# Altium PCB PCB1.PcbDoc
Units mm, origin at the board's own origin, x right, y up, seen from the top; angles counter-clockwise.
Board outline 72.64 x 51.05 mm, 2 copper layers (Top Layer, Bottom Layer); 19 components, 17 nets, 61 pads, 2 vias.
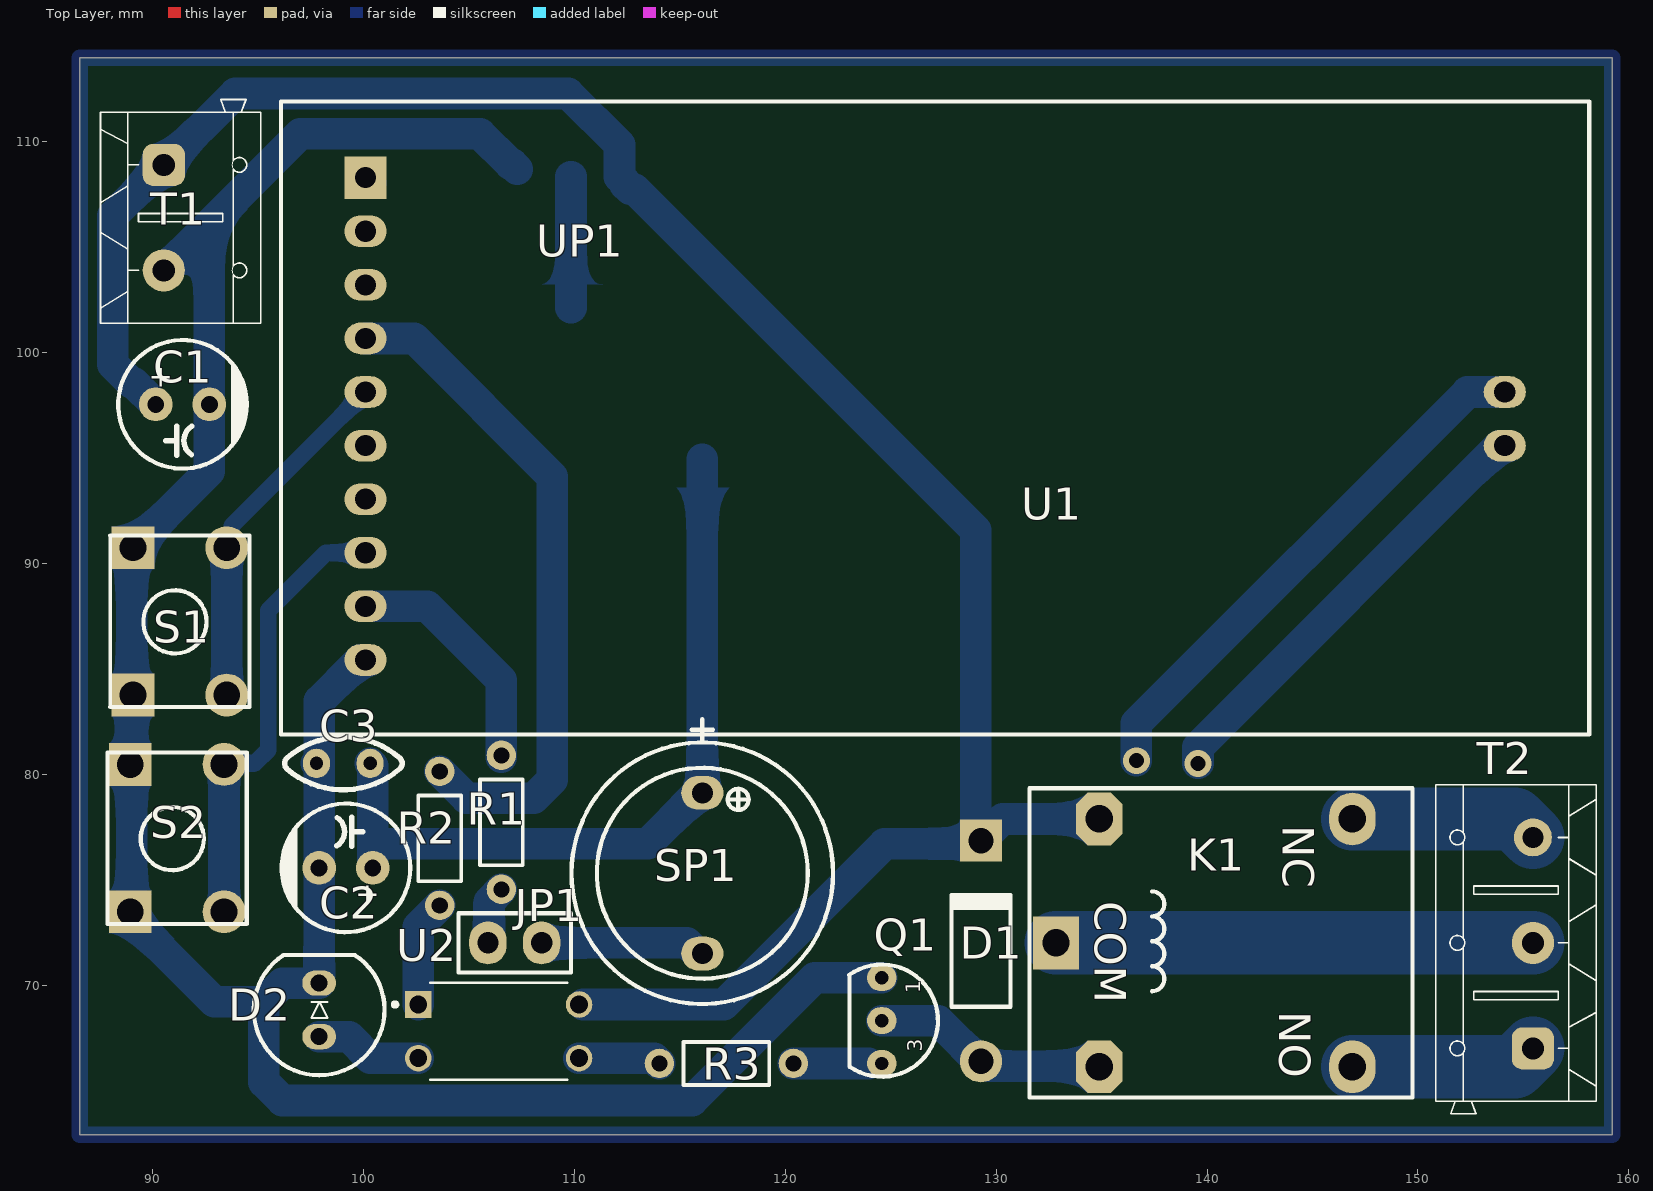
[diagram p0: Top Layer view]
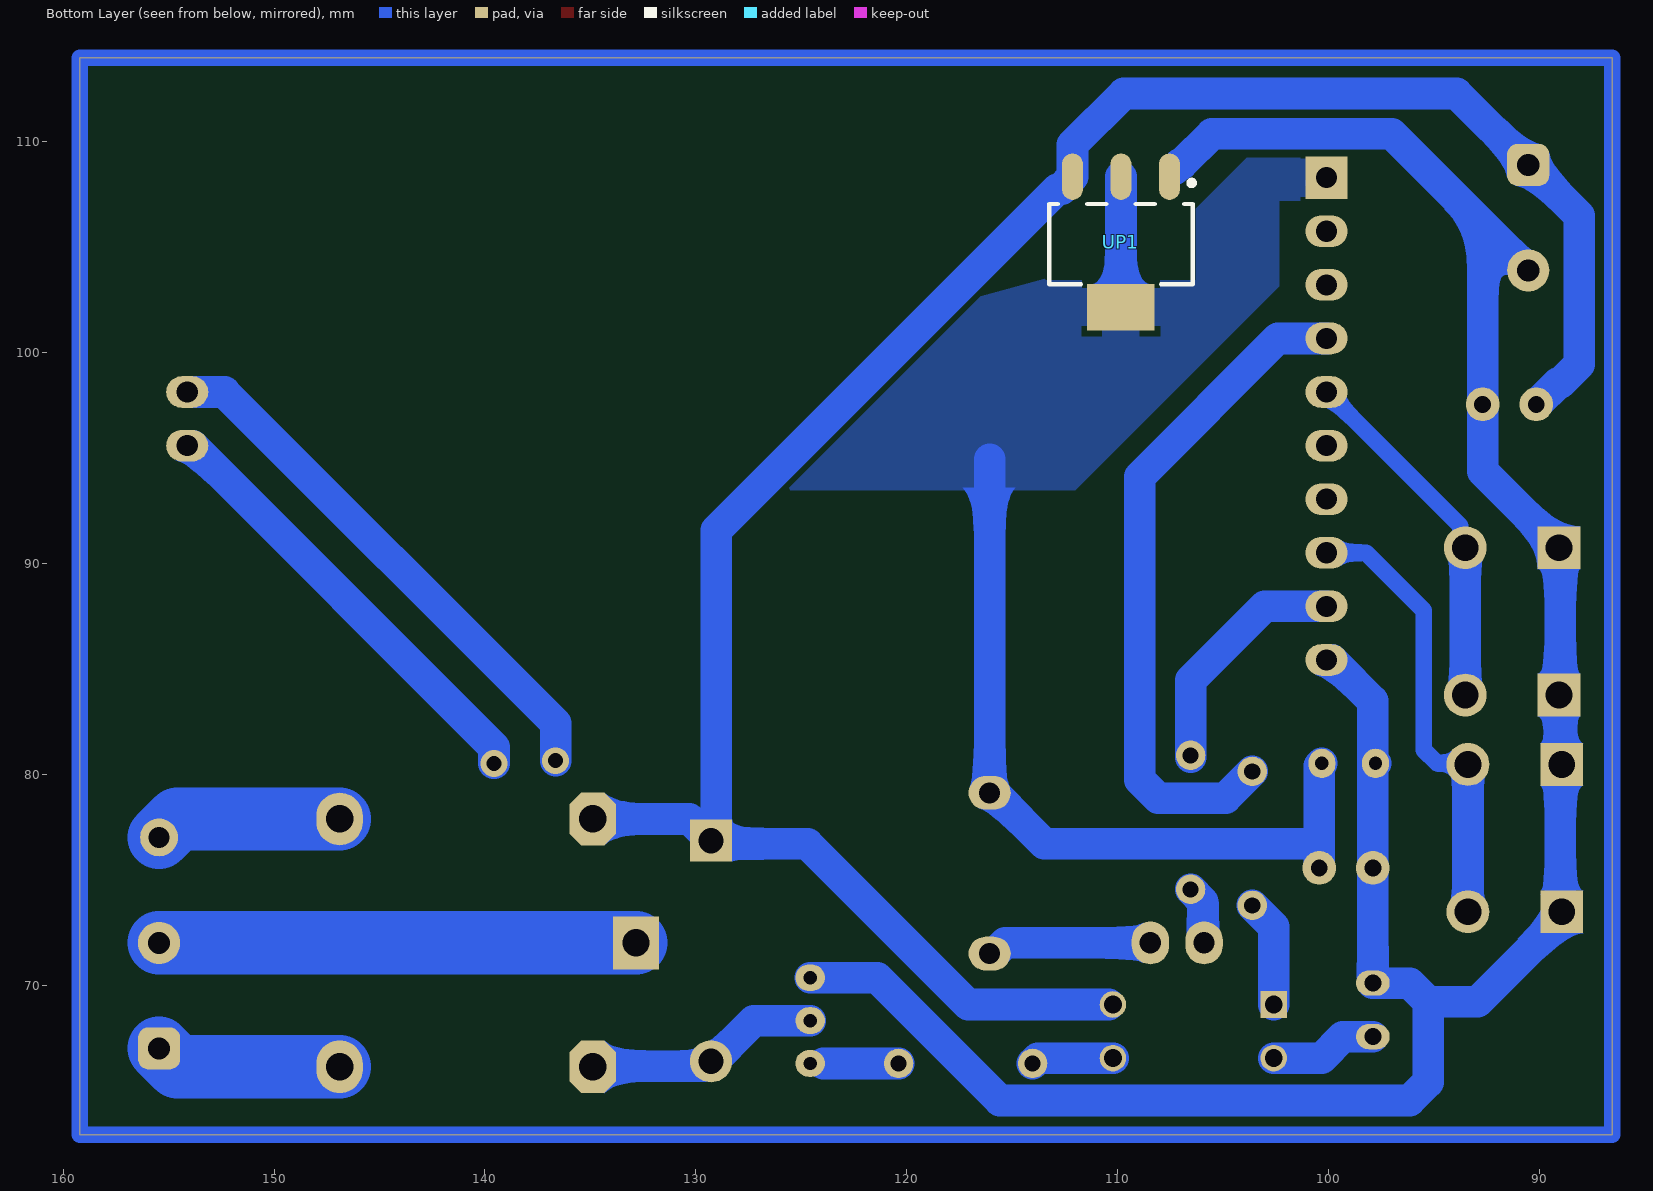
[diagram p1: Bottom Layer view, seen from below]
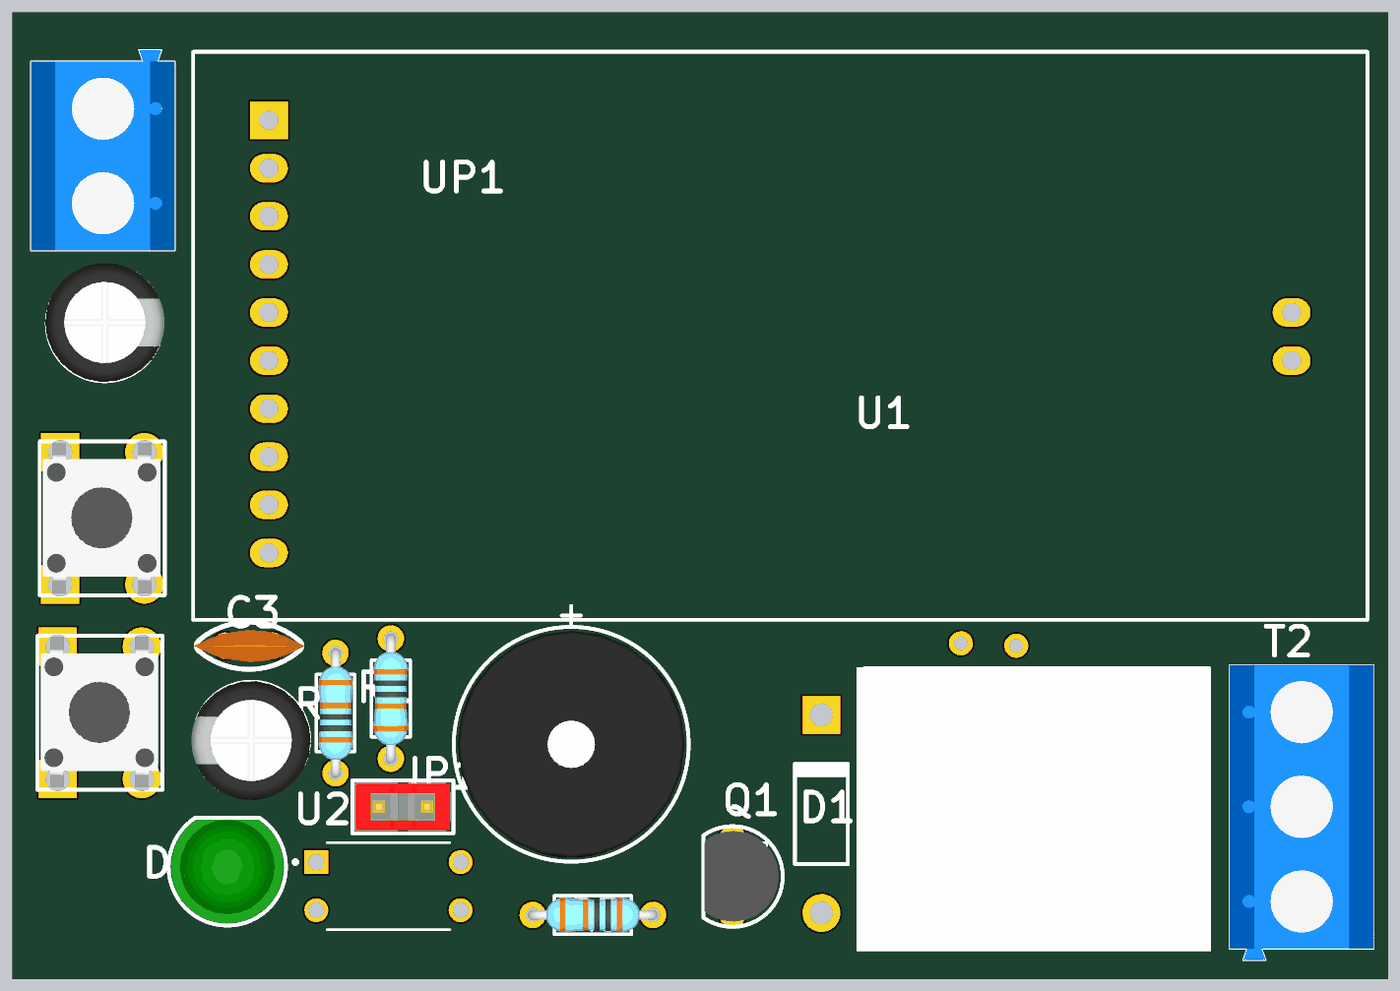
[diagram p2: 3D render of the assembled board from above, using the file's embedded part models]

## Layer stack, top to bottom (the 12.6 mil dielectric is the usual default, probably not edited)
Top Solder: solder mask 0.0102, Solder Resist, Dk 3.5
Top Layer: signal copper 0.0356
Dielectric 1: dielectric 0.32, FR-4, Dk 4.8
Bottom Layer: signal copper 0.0356
Bottom Solder: solder mask 0.0102, Solder Resist, Dk 3.5

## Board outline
86.567,62.912 86.567,113.966 159.211,113.966 159.211,62.912

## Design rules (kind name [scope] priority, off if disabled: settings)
Clearance [All] p1: gap=0.254 ignorepadtopadclearanceinfootprint=FALSE except(0: Arc-Hole Track-Hole SMDPad-Hole THPad-Hole Via-Hole Fill-Hole Poly-Hole Region-Hole Text-Hole)
PolygonConnect [All] p1: connectstyle=Relief reliefconductorwidth=1.8 reliefentries=4 polygonreliefangle="90 Angle" airgapwidth=0.254
RoutingVias [All] p1: holewidth=0.711 width=1.27 viastyle="Through Hole" minholewidth=0.711 minwidth=1.27 maxholewidth=0.711 maxwidth=1.27
SolderMaskExpansion [All] p1: expansion=0.102 istentingtop=FALSE
Width [All] p1: maxlimit=3 minlimit=0.8 preferedwidth=1.5
30 further rules are at their usual default settings.

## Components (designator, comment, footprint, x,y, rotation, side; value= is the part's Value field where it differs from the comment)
C1 "100uf" "Cap electrolitic radial 6.3x12-2.5" 90.17,97.536 r0 top value=1uF
C2 "100uf" "Cap electrolitic radial 6.3x12-2.5" 100.457,75.565 r180 top value=1uF
C3 "100nF" Cap-100nF 99.06,80.518 r0 top
D1 "Diode 1N4007" DO-41 129.286,71.628 r90 top
D2 "LED 5MM" LED5MM_GRN 97.917,68.834 r90 top
JP1 "Jumper 2Pin" "Jumper Small - 2.54 - Black" 107.188,72.009 r180 top
K1 "" "Relay 18.85x15.35x15.70" 139.867,72.009 r270 top
Q1 "C945" C945 124.587,68.326 r90 top
R1 "10" RES-(1/4) 106.553,77.724 r270 top
R2 "1K" RES-(1/4) 103.632,76.962 r90 top
R3 "2.2K" RES-(1/4) 117.221,66.294 r180 top
S1 "Switch PB" "Switch - Push to On" 91.313,87.249 r90 top
S2 "Switch PB" "Switch - Push to On" 91.186,76.975 r90 top
SP1 "" "BUZZER 7.62mm DC" 116.078,75.311 r270 top
T1 "KF301_Terminal" "KF301 2PIN" 90.551,106.386 r270 top
T2 "KF301_Terminal" "KF301 3PIN" 155.448,72.009 r90 top
U1 "RFID" RFID 126.746,96.139 r0 top
U2 "PC817X3NSZ1B" DIP762W50P254L495H455Q4 106.426,67.818 r0 top
UP1 "AMS1117_5V" SOT223 109.855,105.129 r270 bottom

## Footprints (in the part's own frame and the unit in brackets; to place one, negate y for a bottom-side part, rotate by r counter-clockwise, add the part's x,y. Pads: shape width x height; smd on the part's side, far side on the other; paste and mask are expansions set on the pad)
"BUZZER 7.62mm DC" [mm] "BUZZER 12mm DIA , 7.62mm pitch DESIGNER ABBAS BASEREH"
  oval 1.6x2 hole 1: 1(-3.81,0) 2(3.81,0)
  silkscreen extent -7.3,-6.2 6.2,6.2, body extent -6,-6 6,6, height 9.5
C945 [mil] "NPN Transistor"
  oval 50x55 hole 25: 1(80,0) 2(0,0) 3(-80,0)
  silkscreen extent -105,-105 105,61, body extent -94,-96 95,58, height 315
"Cap electrolitic radial 6.3x12-2.5" [mm] "Capacitor Electrolytic D=6.3 x H=12 - P=2.5 mm, Altium Compatible"
  round 1.6 hole 0.8: 1(0,0) 2(2.54,0)
  silkscreen extent -1.77,-3.05 4.32,3.05, body extent -1.87,-3.09 4.43,3.2, height 1.2
Cap-100nF [mil] "Bipolar Capacitor-Design:Ali Hafizi"
  oval 50x55 hole 25: 1(-50,0) 2(50,0)
  silkscreen extent -110,-49 110,49, body extent -115,-34 115,33, height 272
DIP762W50P254L495H455Q4 [mm]
  rect 1.26x1.26 hole 0.84: 1(-3.81,1.27)
  round 1.26 hole 0.84: 2(-3.81,-1.27) 3(3.81,-1.27) 4(3.81,1.27)
  silkscreen extent -5.01,-2.3 3.25,2.3
DO-41 [mm] "Diode, Axial; Body 5.2 x 2.7 mm (LxDia. max), Lead Dia. 0.86 mm (max)"
  round 2 hole 1.2: 1(-5.23,0)
  rect 2x2 hole 1.2: 2(5.23,0)
  silkscreen extent -2.65,-1.4 2.75,1.4
"Jumper Small - 2.54 - Black" [mil] "Designer Abbas Basereh"
  oval 70x80 hole 40: 1(-50,0) 2(50,0)
  silkscreen extent -105,-55 105,55, body extent -100,-50 100,50, height 337
"KF301 2PIN" [mm] "Designer Abbas Basereh"
  rrect50% 2x2 hole 1.05: 1(-2.5,0)
  round 2 hole 1.05: 2(2.5,0)
  silkscreen extent -5.6,-3 5,4.6, body extent -5.6,-3 5,4.6, height 10
"KF301 3PIN" [mm] "Designer Abbas Basereh"
  rrect50% 2x2 hole 1.05: 1(-5,0)
  round 2 hole 1.05: 2(0,0)
  round 1.8 hole 1: 3(5,0)
  silkscreen extent -8.1,-3 7.5,4.6, body extent -8.1,-3 7.5,4.6, height 10
LED5MM_GRN [mm] "LED 5MM THROUGH HOLE GREEN-Designer Abbas Basereh"
  oval 1.2x1.6 hole 0.8: 1(-1.27,0) 2(1.27,0)
  silkscreen extent -3.1,-3.1 2.6,3.1, body extent -3,-3 2.5,3, height 9.14
"Relay 18.85x15.35x15.70" [mm]
  rect 2.5x2.2 hole 1.3: 1(0,-7.025)
  oval 2.5x2.2 hole 1.3: 2(-5.875,7.025) 3(5.875,7.025)
  oct 2.5x2.2 hole 1.3: 4(-5.875,-4.975) 5(5.875,-4.975)
  silkscreen extent -7.32,-8.27 7.32,9.87, body extent -7.37,-8.71 7.63,9.98, height 15.7
RES-(1/4) [mil]
  round 55 hole 30: 1(-125,0) 2(125,0)
  silkscreen extent -80,-40 80,40, body extent -135,-36 135,36, height 115
RFID [mm] "RFID 2&10 PIN"
  rect 2x2 hole 1: 1(-26.632,12.141)
  oval 2x1.5 hole 1: 2(-26.632,9.601) 3(-26.632,7.061) 4(-26.632,4.521) 5(-26.632,1.981) 6(-26.632,-0.559) 7(-26.632,-3.099) 8(-26.632,-5.639) 9(-26.632,-8.179) 10(-26.632,-10.719) 11(27.368,1.981) 12(27.368,-0.559)
  silkscreen extent -30.63,-14.25 31.37,15.75, body extent -30.63,-14.25 31.37,15.72, height 11.1
SOT223 [mm] "SOT223, 4-Leads, Body 6.5x3.5mm, Pitch 2.30mm-Designer Abbas Basereh"
  oval 2.2x1 smd: 1(-3.2,2.3) 2(-3.2,0) 3(-3.2,-2.3)
  rect 2.2x3.2 smd: 4(3,0)
  Top Layer pour cut-out: -1.7,3.556 1.7,3.556 1.7,-3.556 -1.7,-3.556
  silkscreen extent -3.02,-3.4 1.9,3.47, body extent -3.5,-3.25 3.5,3.25, height 1.7
"Switch - Push to On" [mil]
  rect 80x80 hole 50: 1(-137.5,87.5) 1(137.5,87.5)
  round 80 hole 50: 2(-137.5,-87.5) 2(137.5,-87.5)
  silkscreen extent -160,-130 160,130, body extent -155,-121 157,123, height 205

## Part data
C1 C2: library part "Cap ELECTROLITIC TOTAL SIZE", "Cap electrolitic radial"
C3: library part "CAP CERAMIC TOTAL SIZE", "CAP Ceramic Total"
D1: "1 Amp General Purpose Rectifier"
D2: "Light Emitting Diode"
JP1: "Jumper, 2-Pin"
K1: library part RELAY_SPDT, "Single-Pole Dual-Throw Relay"
Q1: "NPN Transistor"
R1 R2 R3: library part "RES DIP PACKAGE", "TOTAL DIP RESISTOR PACK"
S1 S2: "Push Button Switch"
SP1: library part "PIEZO BUZZER", "PIEZO BUZZER ACTIVE"
T1: library part KF301-2Pin_Terminal, "Terminal 2 Pin 250VAC 16A"
T2: library part KF301-3Pin_Terminal, "Terminal 3 Pin 250VAC 16A"
U2: "Optoisolator Transistor Output 1 Channel 4-DIP", Package=None
UP1: library part AMS1117-x.x, "x.x Volt, 800mA Low-Dropout Linear Regulator, 4-pin SOT-223"

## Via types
v1: diameter 1.27, hole 0.711, Top Layer to Bottom Layer, 2 vias

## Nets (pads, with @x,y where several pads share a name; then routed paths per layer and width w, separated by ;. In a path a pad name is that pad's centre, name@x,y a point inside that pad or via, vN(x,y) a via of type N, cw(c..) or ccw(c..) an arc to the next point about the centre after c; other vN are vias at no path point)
+5: C2.1 C3.2 SP1.1 U1.1 UP1.2 UP1.4 | length 44.2
  Bottom Layer w1.5: U1.1 U1.1@100.364,108.03 ; C3.2 100.457,80.391 100.457,76.708 ; C2.1 100.457,76.708 ; UP1.4 UP1.2 ; SP1.1 116.078,94.931 ; SP1.1@116.251,79.121 115.905,79.121 113.492,76.708 100.457,76.708
+12: C1.1 D1.2 K1.4 T1.1 U2.4 UP1.3 | length 105.3
  Bottom Layer w1.5: C1.1 90.143,97.536 89.117,98.562 89.017,98.562 88.138,99.441 88.138,106.473 T1.1 93.933,112.268 109.728,112.268 112.155,109.841 UP1.3 112.405,108.079 112.405,107.979 112.655,107.729 112.87,107.729 129.032,91.567 129.032,77.987 129.036,77.983 129.036,76.708 124.714,76.708 117.094,69.088 U2.4@110.438,69.088 ; D1.2 130.312,77.884 K1.4
GND: C1.2 C2.2 C3.1 D2.2 Q1.1 S1.1 S2.1 T1.2 U1.10 UP1.1 | length 117.8
  Bottom Layer w1.5: T1.2 92.71,106.045 ; U1.10 99.864,85.42 97.917,83.474 97.917,80.645 C3.1 97.917,80.391 C2.2 D2.2 96.167,70.104 95.289,69.225 ; UP1.1@107.305,108.679 107.055,108.929 106.971,108.929 105.537,110.363 97.028,110.363 92.71,106.045 ; Q1.1 121.412,70.358 115.594,64.54 96.167,64.54 95.289,65.419 95.289,69.225 ; 92.71,106.045 C1.2 92.71,94.361 89.09,90.742 89.027,90.678 89.027,83.757 89.027,80.467 89.027,73.546 88.963,73.482 89.229,73.216 89.229,72.95 92.954,69.225 95.289,69.225
NetD1_1: D1.1 K1.5 Q1.2 | length 11.2
  Bottom Layer w1.5: Q1.2 125.222,68.326 127.254,68.326 129.182,66.398 129.421,66.398 129.652,66.167 134.542,66.167 134.575,66.134 K1.5
NetD2_1: D2.1 U2.2 | length 5.1
  Bottom Layer w1.5: D2.1 99.332,67.564 100.348,66.548 U2.2
NetJP1_1: JP1.1 SP1.2 | length 7.8
  Bottom Layer w1.5: JP1.1 115.343,72.009 115.851,71.501 SP1.2
NetJP1_2: JP1.2 R1.2 | length 2.8
  Bottom Layer w1.5: JP1.2 105.971,72.062 105.971,73.967 R1.2
NetK1_1: K1.1 T2.2 | length 22.6
  Bottom Layer w3: K1.1 T2.2
NetK1_2: K1.2 T2.3 | length 8.9
  Bottom Layer w3: K1.2 154.573,77.884 T2.3
NetK1_3: K1.3 T2.1 | length 8.9
  Bottom Layer w3: K1.3 154.573,66.134 T2.1
NetQ1_3: Q1.3 R3.1 | length 3.6
  Bottom Layer w1.5: R3.1 Q1.3@123.952,66.294
NetR1_1: R1.1 U1.9 | length 11.5
  Bottom Layer w1.5: U1.9 103.048,87.96 106.553,84.455 R1.1@106.553,80.808
NetR2_1: R2.1 U2.1 | length 5.1
  Bottom Layer w1.5: U2.1 102.616,72.771 R2.1
NetR2_2: R2.2 U1.4 | length 32.2
  Bottom Layer w1.5: U1.4 102.413,100.66 108.966,94.107 108.966,79.746 108.087,78.867 104.902,78.867 R2.2
NetR3_2: R3.2 U2.3 | length 3.9
  Bottom Layer w1.5: U2.3 113.792,66.548 R3.2
NetS1_2: S1.2 U1.5 | length 17.3
  Bottom Layer w0.8: S1.2@93.535,90.614 93.771,90.85 93.771,91.778 99.514,97.52 99.514,97.581 100.053,98.12 U1.5
  Bottom Layer w1.5: S1.2@93.535,83.757 93.535,90.614 S1.2@93.535,90.742
NetS2_2: S2.2 U1.8 | length 21.7
  Bottom Layer w0.8: S2.2@93.408,80.467 93.471,80.529 94.88,80.529 95.504,81.153 95.504,87.757 98.247,90.5 U1.8
  Bottom Layer w1.5: S2.2@93.408,73.482 S2.2@93.408,80.467
pads on no net: U1.2 U1.3 U1.6 U1.7 U1.11 U1.12
copper on no net: | length 294.4
  Bottom Layer w0.8: 86.567,62.912 86.567,113.966 159.211,113.966 159.211,62.912 86.567,62.912
  Bottom Layer w1.5: v1(136.652,80.645) 136.652,82.423 152.349,98.12 154.114,98.12 ; v1(139.573,80.518) 139.573,81.28 153.864,95.571 153.864,95.58 154.114,95.58

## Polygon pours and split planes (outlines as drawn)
+5 on Bottom Layer "NONET_L-01_P-001" (solid, remove dead copper, pour order 0): 99.06,109.22 103.886,109.22 108.204,104.902 123.613,100.753 126.779,93.472 112.014,93.472 102.362,103.124 102.362,107.188 99.06,107.188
